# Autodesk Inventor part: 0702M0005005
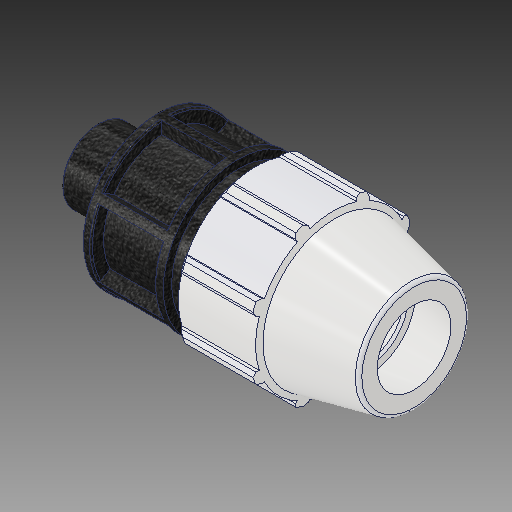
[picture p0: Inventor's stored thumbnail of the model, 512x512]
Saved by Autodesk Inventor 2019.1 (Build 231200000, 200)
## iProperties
Created: 2017-02
Part Number: 0702M0005005
Material: PVC-Piping
Description: PLASSON MALE ADAPTOR 1/2'' - 1/2''M
Document SubType Name: Modeling
Designer: KIM
Mass: 92.6774 g
Surface Area: 199.44 cm^2
Volume: 66.1981 cm^3
Density: 1.4 g/cm^3
Appearance: PTFE
Author: KIM
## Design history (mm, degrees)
derived "0702M0.ipt"
feature "Solid1::0702M0.ipt"
tag "TaggingFeature1"
body "Solid1"
other parameters: "d2" = 21.2, "d4" = 12.99029, "d5" = 22.733, "d7" = 48.006, "d8" = 36.0045, "d9" = 12.99029, "d11" = 2.59806, "d12" = 38.4048, "d13" = 120 deg, "d14" = 31.8, "d15" = 12 deg, "d16" = 43.2054, "d18" = 1.06, "d19" = 35 deg, "d20" = 17.5 deg, "d21" = 44.64558, "d23" = 0, "d25" = 360 deg, "d27" = 0.96012, "d34" = 2.4003, "d36" = 0, "d42" = 22.733, "d43" = 1.44018, "d46" = 0.636, "d49" = 70.104, "d51" = 90.932, "d52" = 17.018, "d53" = 0.424, "d55" = 360 deg, "d57" = 20.955, "d58" = 14.6685, "d59" = 18.1864, "d_" = 21.2, "E_" = 48.006, "H_" = 90.932, "l_" = 70.104, "l_2" = 17.018, "G_" = 20.955
